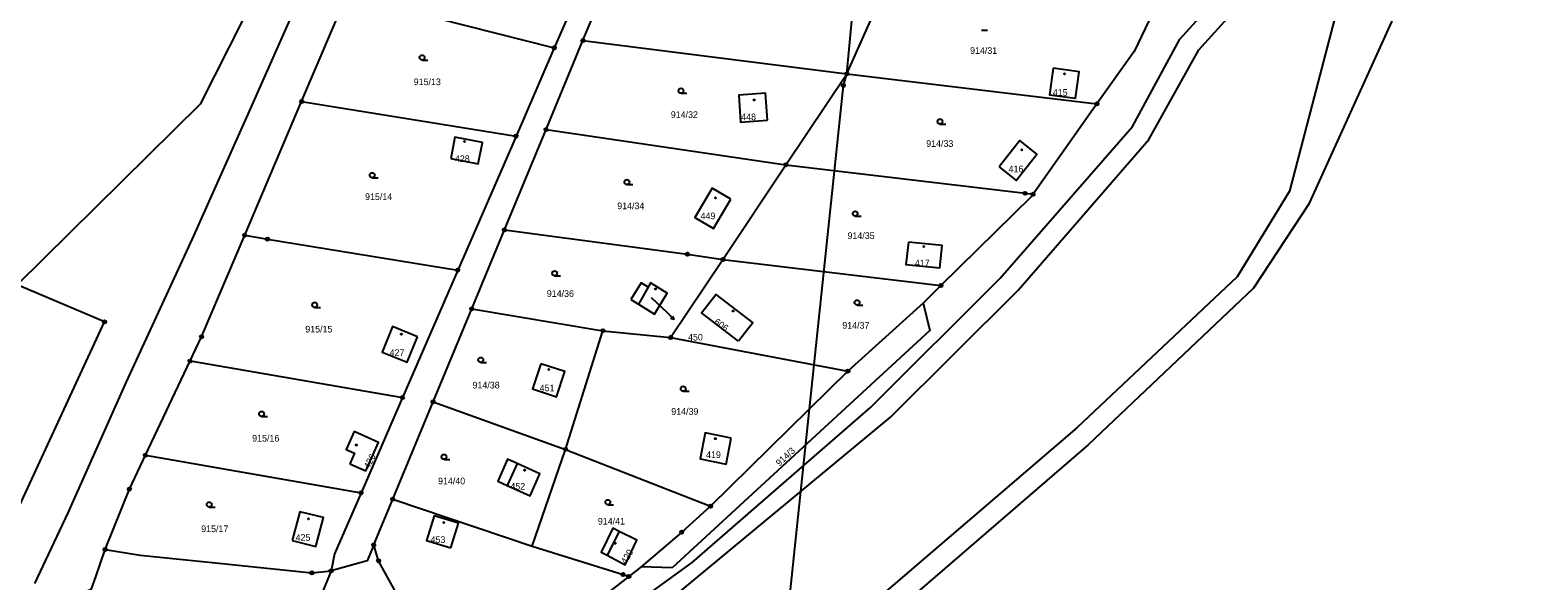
# Model space of a CAD drawing. Extents: x -745926 to -742978, y -968282 to -965689.
# Drawn here: x -744207.1 to -743979.6, y -968122 to -968038.9 of the extents above; entities that cross this region are included whole.
import ezdxf

# ---------------------------------------------------------------- set-up
doc = ezdxf.new("R2010")
doc.units = 0
for name, color, linetype in [('Hranice parcel', 7, 'Continuous'), ('Parcelní čísla', 7, 'Continuous'), ('Pop  PČ popisy', 7, 'Continuous'), ('Poz předměty', 7, 'Continuous'), ('Vnitřní kresba', 7, 'Continuous'), ('Značky bodu BP', 7, 'Continuous'), ('Značky budov', 7, 'Continuous'), ('Značky kultur', 7, 'Continuous')]:
    doc.layers.add(name, color=color, linetype=linetype)

msp = doc.modelspace()

# ---------------------------------------------------------------- linework, layer by layer
at = {"layer": 'Hranice parcel'}
for p, q in [((-744120.78, -968025.01), (-744128, -968041.62)), ((-744123.68, -968040.51), (-744117.37, -968025.32)), ((-744083.85, -968045.5), (-744077.16, -968030.5)), ((-744166.12, -968049.71), (-744159.3, -968033.67)), ((-744159.3, -968033.67), (-744128, -968041.62)), ((-744129.24, -968053.92), (-744123.68, -968040.51)), ((-744123.68, -968040.51), (-744083.85, -968045.5)), ((-744128, -968041.62), (-744133.77, -968054.91)), ((-744093.05, -968059.24), (-744083.85, -968045.5)), ((-744083.85, -968045.5), (-744046.13, -968050.07)), ((-744174.69, -968069.87), (-744166.12, -968049.71)), ((-744166.12, -968049.71), (-744133.77, -968054.91)), ((-744046.13, -968050.07), (-744055.77, -968063.68)), ((-744135.52, -968069.06), (-744129.24, -968053.92)), ((-744129.24, -968053.92), (-744093.05, -968059.24)), ((-744133.77, -968054.91), (-744142.56, -968075.12)), ((-744102.57, -968073.53), (-744093.05, -968059.24)), ((-744022.49, -968077.78), (-744014.05, -968065.04)), ((-744140.46, -968080.96), (-744135.52, -968069.06)), ((-744142.56, -968075.12), (-744150.91, -968094.33)), ((-744110.46, -968085.28), (-744102.57, -968073.53)), ((-744102.57, -968073.53), (-744069.66, -968077.46)), ((-744069.66, -968077.46), (-744072.33, -968080.09)), ((-744041.65, -968095.96), (-744022.49, -968077.78)), ((-744146.27, -968094.96), (-744140.46, -968080.96)), ((-744140.46, -968080.96), (-744120.66, -968084.25)), ((-744072.33, -968080.09), (-744083.69, -968090.33)), ((-744126.29, -968102.14), (-744120.66, -968084.25)), ((-744120.66, -968084.25), (-744110.46, -968085.28)), ((-744110.46, -968085.28), (-744083.69, -968090.33)), ((-744189.68, -968103.04), (-744182.93, -968088.82)), ((-744182.93, -968088.82), (-744150.91, -968094.33)), ((-744083.69, -968090.33), (-744104.43, -968110.72)), ((-744150.91, -968094.33), (-744157.15, -968108.69)), ((-744152.37, -968109.66), (-744146.27, -968094.96)), ((-744146.27, -968094.96), (-744126.29, -968102.14)), ((-744041.65, -968095.96), (-744047.45, -968101.47)), ((-744131.35, -968116.76), (-744126.29, -968102.14)), ((-744126.29, -968102.14), (-744104.43, -968110.72)), ((-744047.45, -968101.47), (-744076.77, -968126.75)), ((-744189.68, -968103.04), (-744157.15, -968108.69)), ((-744155.23, -968116.56), (-744152.37, -968109.66)), ((-744152.37, -968109.66), (-744131.35, -968116.76)), ((-744104.43, -968110.72), (-744108.76, -968114.62)), ((-744108.76, -968114.62), (-744114.89, -968119.86)), ((-744195.77, -968117.23), (-744190.47, -968118.1)), ((-744161.67, -968120.48), (-744165.1, -968128.74)), ((-744164.55, -968120.76), (-744161.67, -968120.48)), ((-744114.89, -968119.86), (-744116.75, -968121.3)), ((-744110.22, -968120.01), (-744114.89, -968119.86)), ((-744116.75, -968121.3), (-744140.72, -968139.9))]:
    msp.add_line(p, q, dxfattribs=at)
for points in [[(-744117.58, -967853.4), (-744114.86, -967857.67), (-744123.11, -967907.49), (-744132.93, -967940.54), (-744143.32, -967968.25), (-744148.69, -967985.38), (-744181.44, -968050.09), (-744209.04, -968077.36)], [(-744014.05, -968065.04), (-744001.65, -968037.67), (-743984.6, -967960.81), (-743979.62, -967902.8), (-743981.26, -967873.23)], [(-744238.47, -968250.81), (-744228.48, -968220.23), (-744215.49, -968202.15), (-744184.43, -968175.45), (-744137.25, -968142.28), (-744118.9, -968127.71), (-744107.2, -968119.2), (-744080.31, -968095.84), (-744060.74, -968076.33), (-744040.78, -968053.44), (-744033.64, -968040.28), (-744026.79, -968032.71), (-744019.73, -968009.91)], [(-744037.77, -968036.4), (-744040.52, -968042.14), (-744046.13, -968050.07)], [(-744052.74, -968044.67), (-744053.29, -968048.68), (-744049.38, -968049.21), (-744048.83, -968045.21), (-744052.74, -968044.67)], [(-744095.83, -968052.52), (-744096.11, -968048.46), (-744100.17, -968048.74), (-744099.9, -968052.8), (-744095.83, -968052.52)], [(-744143.62, -968058.31), (-744139.46, -968059.11), (-744138.84, -968055.88), (-744143, -968055.08), (-744143.62, -968058.31)], [(-744060.9, -968059.56), (-744058.31, -968061.6), (-744055.18, -968057.62), (-744057.77, -968055.59), (-744060.9, -968059.56)], [(-744093.05, -968059.24), (-744056.97, -968063.54), (-744055.77, -968063.68)], [(-744101.36, -968064.43), (-744104.2, -968062.76), (-744106.8, -968067.16), (-744103.96, -968068.84), (-744101.36, -968064.43)], [(-744055.77, -968063.68), (-744056, -968064), (-744069.66, -968077.46)], [(-744182.93, -968088.82), (-744181.2, -968085.17), (-744174.69, -968069.87)], [(-744174.69, -968069.87), (-744171.26, -968070.43), (-744142.56, -968075.12)], [(-744135.52, -968069.06), (-744107.91, -968072.73), (-744102.57, -968073.53)], [(-744074.58, -968070.9), (-744074.97, -968074.26), (-744069.85, -968074.78), (-744069.5, -968071.43), (-744074.58, -968070.9)], [(-744209.89, -968113.26), (-744195.85, -968082.93), (-744209.04, -968077.36)], [(-744116.45, -968079.57), (-744115.3, -968080.27), (-744112.9, -968081.74), (-744110.97, -968078.58), (-744113.46, -968077.06), (-744113.85, -968077.7), (-744114.91, -968077.05), (-744116.45, -968079.57)], [(-744100.21, -968085.83), (-744105.77, -968081.58), (-744103.64, -968078.78), (-744098.04, -968083.05), (-744100.21, -968085.83)], [(-744072.33, -968080.09), (-744071.34, -968084.2), (-744110.22, -968120.01)], [(-744148.61, -968085.18), (-744152.42, -968083.64), (-744153.98, -968087.47), (-744150.17, -968089.01), (-744148.61, -968085.18)], [(-744130.02, -968089.23), (-744131.27, -968093.03), (-744127.64, -968094.22), (-744126.4, -968090.42), (-744130.02, -968089.23)], [(-744158.86, -968104.33), (-744156.44, -968105.38), (-744154.53, -968101.1), (-744158.19, -968099.46), (-744159.39, -968102.14), (-744158.12, -968102.71), (-744158.86, -968104.33)], [(-744101.3, -968100.43), (-744105.23, -968099.67), (-744106, -968103.59), (-744102.06, -968104.36), (-744101.3, -968100.43)], [(-744195.77, -968117.23), (-744192.09, -968108.13), (-744189.68, -968103.04)], [(-744133.62, -968104.28), (-744135.03, -968103.64), (-744136.53, -968106.96), (-744135.11, -968107.6), (-744131.64, -968109.15), (-744130.2, -968105.81), (-744133.62, -968104.28)], [(-744157.15, -968108.69), (-744161.15, -968117.89), (-744161.67, -968120.48)], [(-744167.54, -968115.9), (-744163.95, -968116.81), (-744162.83, -968112.4), (-744166.39, -968111.55), (-744167.54, -968115.9)], [(-744143.58, -968117.01), (-744142.44, -968113.28), (-744146.14, -968112.15), (-744147.29, -968115.88), (-744143.58, -968117.01)], [(-744120.02, -968118.12), (-744117.29, -968119.54), (-744115.52, -968115.85), (-744118.2, -968114.51), (-744119.14, -968114.04), (-744120.93, -968117.66), (-744120.02, -968118.12)], [(-744204.66, -968135.98), (-744200.78, -968124.59), (-744197.81, -968123.17), (-744197.17, -968121.38), (-744195.77, -968117.23)], [(-744190.47, -968118.1), (-744178.59, -968119.32), (-744164.55, -968120.76)], [(-744155.23, -968116.56), (-744156.22, -968118.94), (-744161.67, -968120.48)], [(-744140.72, -968139.9), (-744142.07, -968139.07), (-744144.1, -968137.82), (-744154.5, -968118.94), (-744155.23, -968116.56)], [(-744131.35, -968116.76), (-744122.15, -968119.62), (-744117.63, -968121.03), (-744116.75, -968121.3)]]:
    msp.add_lwpolyline(points, dxfattribs=at)
at = {"layer": 'Pop  PČ popisy'}
for p, q in [((-744113.37, -968079.25), (-744110.99, -968081.53)), ((-744110.99, -968081.53), (-744109.91, -968082.57)), ((-744109.91, -968082.57), (-744110.45, -968082.4)), ((-744109.91, -968082.57), (-744110.1, -968082.04))]:
    msp.add_line(p, q, dxfattribs=at)
at = {"layer": 'Poz předměty'}
for p, q in [((-744144.01, -967983.46), (-744174.25, -968051.59)), ((-744094.29, -968141.73), (-744084.39, -968047.28)), ((-744174.25, -968051.59), (-744182.63, -968070.41)), ((-744182.63, -968070.41), (-744192.57, -968091.94)), ((-744192.57, -968091.94), (-744201.4, -968111.73)), ((-744201.4, -968111.73), (-744206.41, -968122.38))]:
    msp.add_line(p, q, dxfattribs=at)
msp.add_lwpolyline([(-744084.39, -968047.28), (-744083.85, -968045.5), (-744074.63, -967947.55)], dxfattribs=at)
for radius in [0.25, 0.2, 0.15, 0.1, 0.05]:
    msp.add_circle((-744084.39, -968047.28), radius, dxfattribs=at)
at = {"layer": 'Vnitřní kresba'}
for p, q in [((-743990.05, -967960.19), (-744017.1, -968063.19)), ((-744030.76, -968041.91), (-744023.98, -968034.39)), ((-744038.28, -968055.4), (-744030.76, -968041.91)), ((-744058.02, -968078.12), (-744038.28, -968055.4)), ((-744017.1, -968063.19), (-744024.97, -968076.14)), ((-744024.97, -968076.14), (-744049.18, -968098.91)), ((-744113.85, -968077.7), (-744115.3, -968080.27)), ((-744077.27, -968097.3), (-744058.02, -968078.12)), ((-744115.32, -968128.74), (-744077.27, -968097.3)), ((-744049.18, -968098.91), (-744094.87, -968138.01)), ((-744133.62, -968104.28), (-744135.11, -968107.6)), ((-744118.2, -968114.51), (-744120.02, -968118.12))]:
    msp.add_line(p, q, dxfattribs=at)
at = {"layer": 'Značky bodu BP'}
for centre, radius in [((-744123.68, -968040.51), 0.25), ((-744123.68, -968040.51), 0.0152), ((-744128, -968041.62), 0.25), ((-744128, -968041.62), 0.0152), ((-744083.85, -968045.5), 0.25), ((-744083.85, -968045.5), 0.0152), ((-744166.12, -968049.71), 0.25), ((-744166.12, -968049.71), 0.0152), ((-744046.13, -968050.07), 0.25), ((-744046.13, -968050.07), 0.0152), ((-744133.77, -968054.91), 0.25), ((-744129.24, -968053.92), 0.25), ((-744129.24, -968053.92), 0.0152), ((-744133.77, -968054.91), 0.0152), ((-744093.05, -968059.24), 0.25), ((-744093.05, -968059.24), 0.0152), ((-744056.97, -968063.54), 0.25), ((-744056.97, -968063.54), 0.0152), ((-744055.77, -968063.68), 0.25), ((-744055.77, -968063.68), 0.0152), ((-744174.69, -968069.87), 0.25), ((-744174.69, -968069.87), 0.0152), ((-744171.26, -968070.43), 0.25), ((-744171.26, -968070.43), 0.0152), ((-744135.52, -968069.06), 0.25), ((-744135.52, -968069.06), 0.0152), ((-744107.91, -968072.73), 0.25), ((-744107.91, -968072.73), 0.0152), ((-744142.56, -968075.12), 0.25), ((-744142.56, -968075.12), 0.0152), ((-744102.57, -968073.53), 0.25), ((-744102.57, -968073.53), 0.0152), ((-744069.66, -968077.46), 0.25), ((-744069.66, -968077.46), 0.0152), ((-744140.46, -968080.96), 0.25), ((-744140.46, -968080.96), 0.0152), ((-744195.85, -968082.93), 0.25), ((-744195.85, -968082.93), 0.0152), ((-744120.66, -968084.25), 0.25), ((-744120.66, -968084.25), 0.0152), ((-744181.2, -968085.17), 0.25), ((-744181.2, -968085.17), 0.0152), ((-744110.46, -968085.28), 0.25), ((-744110.46, -968085.28), 0.0152), ((-744182.93, -968088.82), 0.25), ((-744182.93, -968088.82), 0.0152), ((-744083.69, -968090.33), 0.25), ((-744083.69, -968090.33), 0.0152), ((-744150.91, -968094.33), 0.25), ((-744150.91, -968094.33), 0.0152), ((-744146.27, -968094.96), 0.25), ((-744146.27, -968094.96), 0.0152), ((-744126.29, -968102.14), 0.25), ((-744126.29, -968102.14), 0.0152), ((-744189.68, -968103.04), 0.25), ((-744189.68, -968103.04), 0.0152), ((-744192.09, -968108.13), 0.25), ((-744192.09, -968108.13), 0.0152), ((-744157.15, -968108.69), 0.25), ((-744157.15, -968108.69), 0.0152), ((-744152.37, -968109.66), 0.25), ((-744152.37, -968109.66), 0.0152), ((-744104.43, -968110.72), 0.25), ((-744104.43, -968110.72), 0.0152), ((-744108.76, -968114.62), 0.25), ((-744108.76, -968114.62), 0.0152), ((-744195.77, -968117.23), 0.25), ((-744195.77, -968117.23), 0.0152), ((-744155.23, -968116.56), 0.25), ((-744155.23, -968116.56), 0.0152), ((-744164.55, -968120.76), 0.25), ((-744161.67, -968120.48), 0.25), ((-744161.67, -968120.48), 0.0152), ((-744154.5, -968118.94), 0.25), ((-744154.5, -968118.94), 0.0152), ((-744164.55, -968120.76), 0.0152), ((-744117.63, -968121.03), 0.25), ((-744117.63, -968121.03), 0.0152), ((-744116.75, -968121.3), 0.25), ((-744116.75, -968121.3), 0.0152)]:
    msp.add_circle(centre, radius, dxfattribs=at)
at = {"layer": 'Značky budov'}
for centre in [(-744051.04, -968045.53), (-744097.85, -968049.47), (-744141.55, -968055.72), (-744057.47, -968056.98), (-744103.68, -968064.21), (-744072.25, -968071.57), (-744112.73, -968077.97), (-744101.01, -968081.28), (-744151.06, -968084.77), (-744128.81, -968090.09), (-744157.85, -968101.49), (-744103.71, -968100.53), (-744132.47, -968105.27), (-744165.07, -968112.61), (-744144.67, -968113.18), (-744118.8, -968116.32)]:
    msp.add_circle(centre, 0.0875, dxfattribs=at)
at = {"layer": 'Značky kultur'}
for p, q in [((-744063.54, -968038.94), (-744062.66, -968038.94)), ((-744147.93, -968043.45), (-744147.05, -968043.45)), ((-744108.88, -968048.46), (-744108, -968048.46)), ((-744069.81, -968053.09), (-744068.93, -968053.09)), ((-744155.46, -968061.2), (-744154.58, -968061.2)), ((-744117.05, -968062.22), (-744116.17, -968062.22)), ((-744082.6, -968066.99), (-744081.72, -968066.99)), ((-744127.94, -968075.98), (-744127.06, -968075.98)), ((-744164.15, -968080.74), (-744163.27, -968080.74)), ((-744082.31, -968080.39), (-744081.43, -968080.39)), ((-744139.08, -968089.04), (-744138.2, -968089.04)), ((-744108.55, -968093.38), (-744107.67, -968093.38)), ((-744172.15, -968097.18), (-744171.27, -968097.18)), ((-744144.63, -968103.65), (-744143.75, -968103.65)), ((-744180.05, -968110.84), (-744179.17, -968110.84)), ((-744119.92, -968110.49), (-744119.04, -968110.49))]:
    msp.add_line(p, q, dxfattribs=at)
for centre in [(-744147.93, -968043.07), (-744108.88, -968048.08), (-744069.81, -968052.71), (-744155.46, -968060.82), (-744117.05, -968061.84), (-744082.6, -968066.61), (-744127.94, -968075.6), (-744082.31, -968080.01), (-744164.15, -968080.36), (-744139.08, -968088.66), (-744108.55, -968093), (-744172.15, -968096.8), (-744144.63, -968103.27), (-744180.05, -968110.46), (-744119.92, -968110.11)]:
    msp.add_circle(centre, 0.375, dxfattribs=at)

# ---------------------------------------------------------------- texts
at = {"layer": 'Parcelní čísla'}
for s, p in [('914/31', (-744065.27, -968042.51)), ('915/13', (-744149.2, -968047.23)), ('415', (-744052.79, -968048.83)), ('914/32', (-744110.42, -968052.17)), ('448', (-744099.8, -968052.51)), ('914/33', (-744071.89, -968056.53)), ('428', (-744142.99, -968058.82)), ('416', (-744059.46, -968060.36)), ('915/14', (-744156.54, -968064.54)), ('914/34', (-744118.5, -968065.93)), ('449', (-744105.93, -968067.44)), ('914/35', (-744083.76, -968070.43)), ('417', (-744073.6, -968074.55)), ('914/36', (-744129.12, -968079.15)), ('915/15', (-744165.56, -968084.52)), ('914/37', (-744084.55, -968083.95)), ('450', (-744107.82, -968085.73)), ('427', (-744152.83, -968088.06)), ('914/38', (-744140.33, -968092.96)), ('451', (-744130.2, -968093.38)), ('914/39', (-744110.35, -968096.93)), ('915/16', (-744173.57, -968100.97)), ('419', (-744105.1, -968103.45)), ('914/40', (-744145.53, -968107.41)), ('452', (-744134.62, -968108.22)), ('915/17', (-744181.26, -968114.62)), ('914/41', (-744121.42, -968113.48)), ('425', (-744167.02, -968115.93)), ('453', (-744146.66, -968116.26))]:
    msp.add_text(s, height=1, dxfattribs=at).set_placement(p)
for s, rotation, p in [('606', 324, (-744103.99, -968083.12)), ('914/3', 43, (-744094.02, -968104.75)), ('426', 64, (-744155.88, -968105.14)), ('420', 60, (-744117.15, -968119.52))]:
    msp.add_text(s, height=1, rotation=rotation, dxfattribs=at).set_placement(p)

doc.saveas('drawing.dxf')
